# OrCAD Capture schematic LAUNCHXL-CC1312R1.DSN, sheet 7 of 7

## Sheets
7 1_RF: size A3
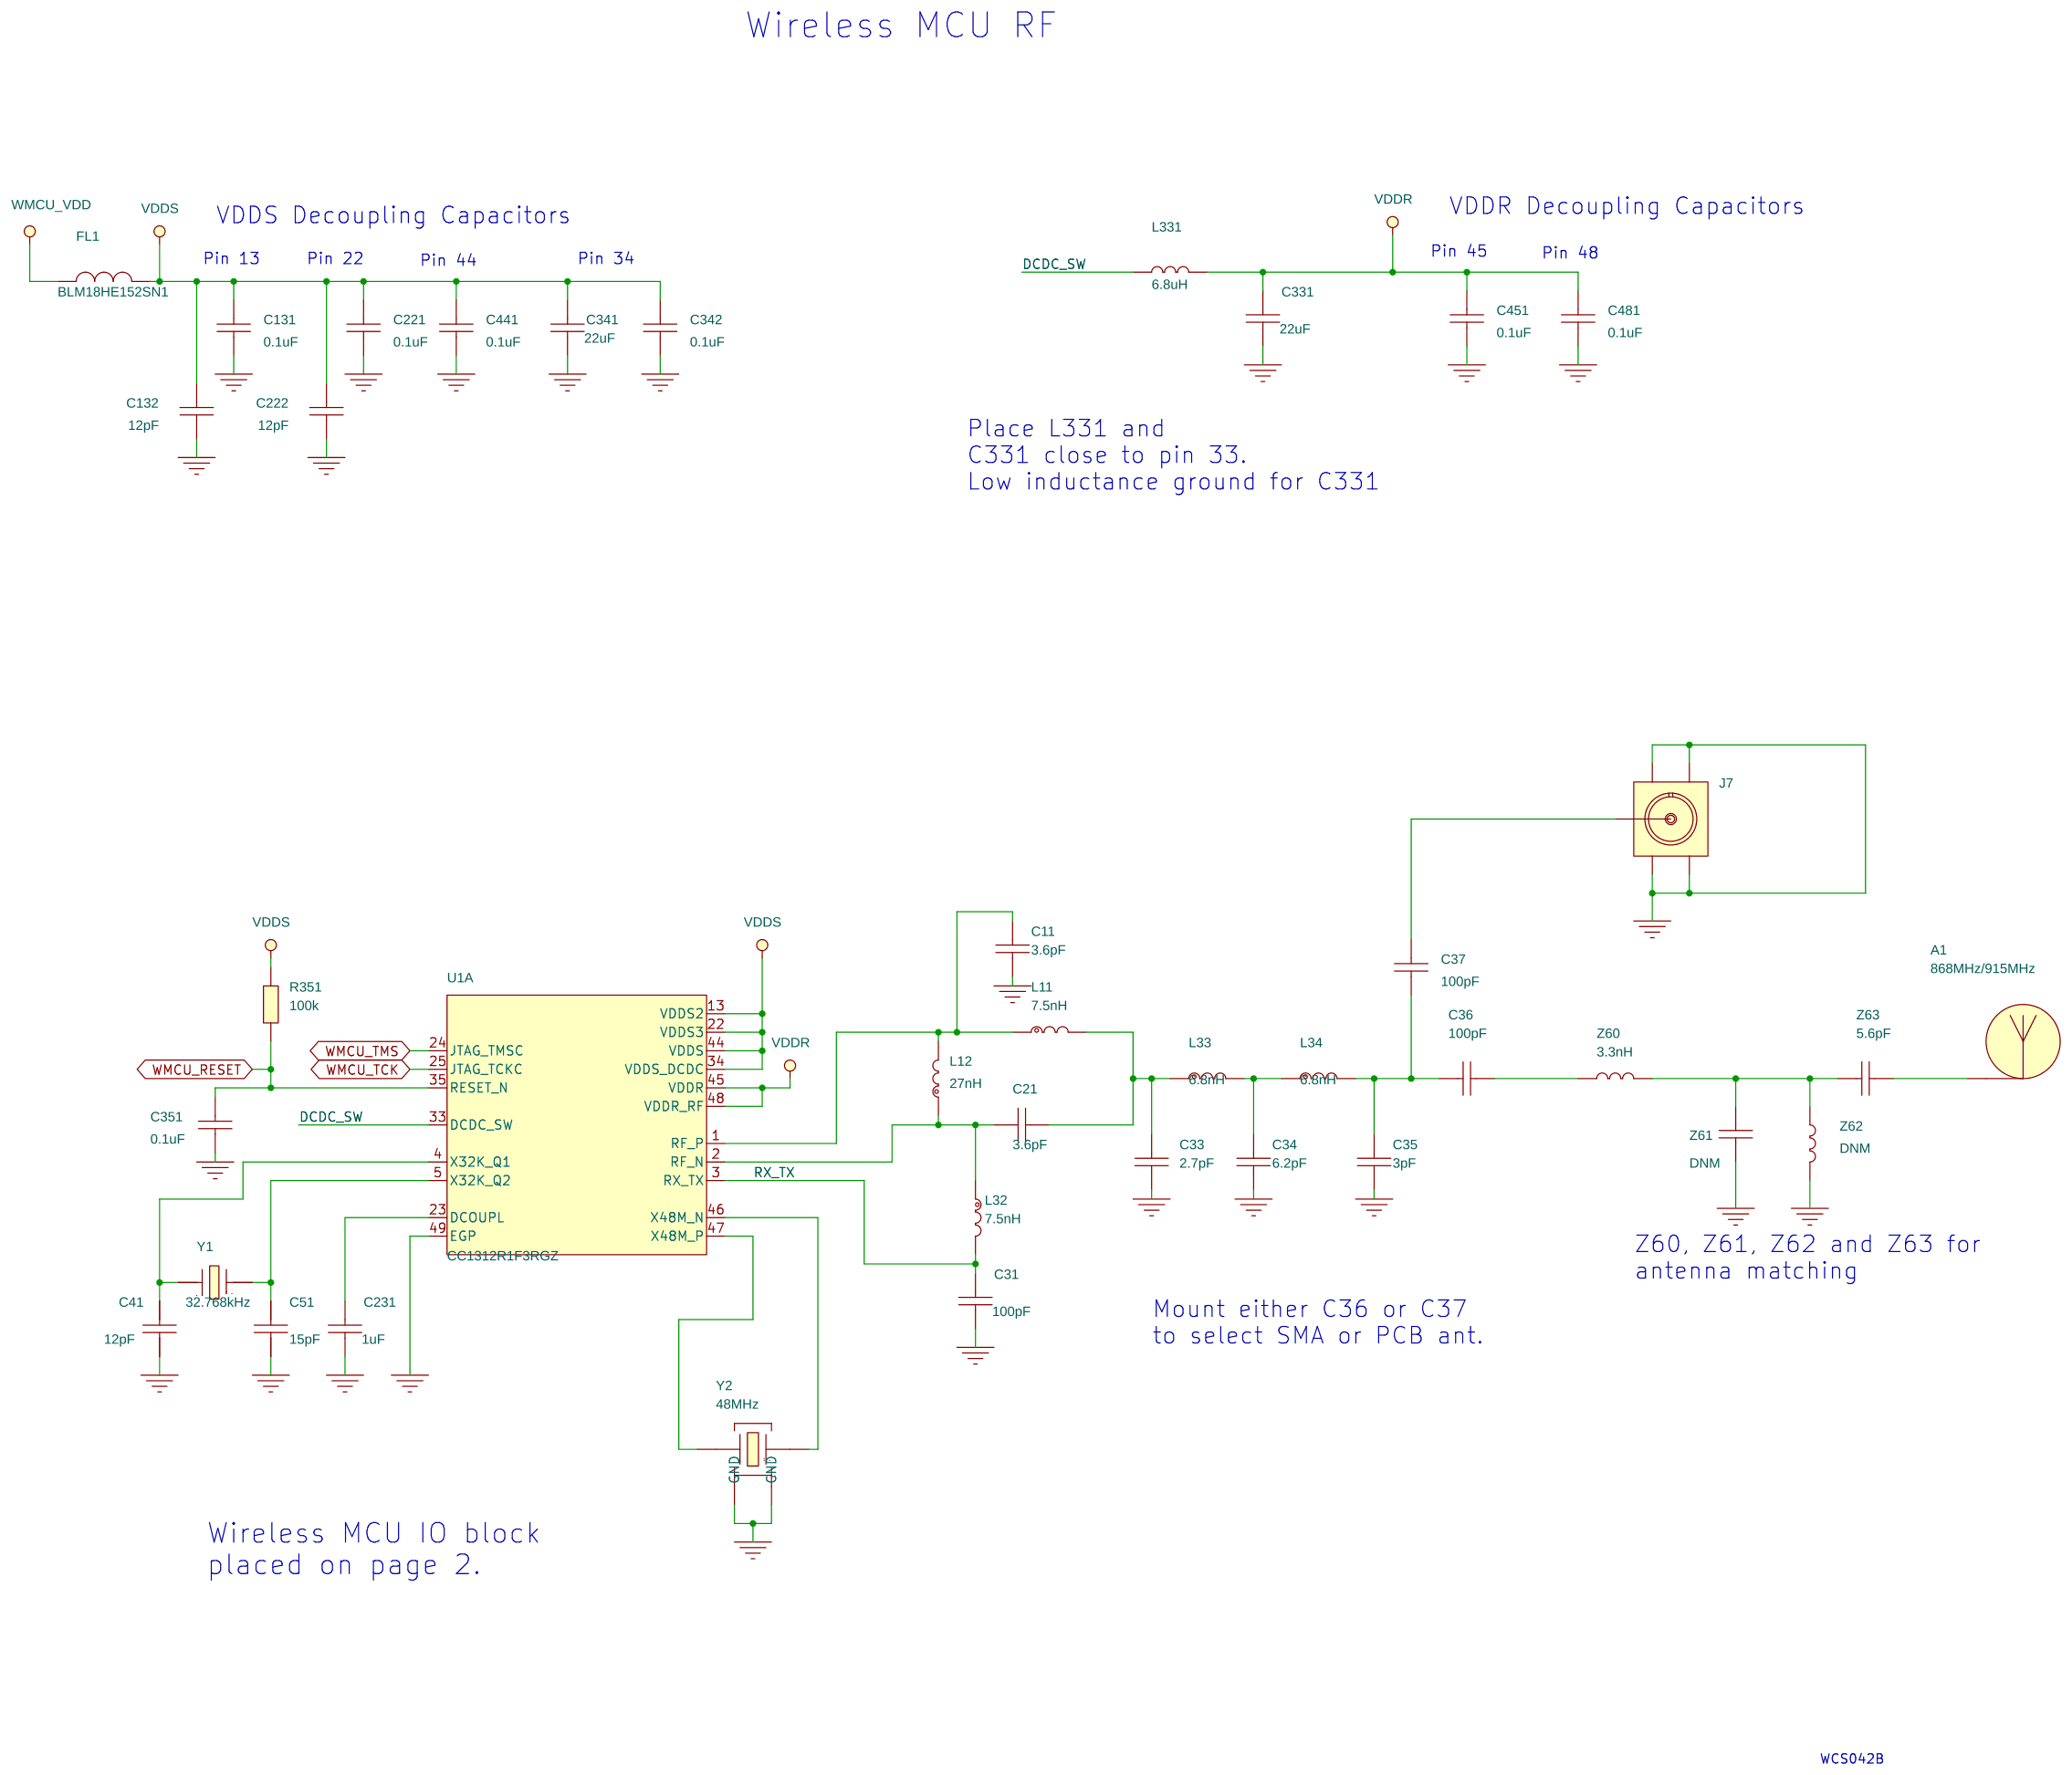
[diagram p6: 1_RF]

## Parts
sheet 1_RF
A1  868MHz/915MHz  [ANTENNA_DN024N]
C11  3.6pF  [CAPC1005X60B2N]
C21  3.6pF  [CAPC1005X60B2N]
C31  100pF  [CAPC1005X60B2N]
C33  2.7pF  [CAPC1005X60B2N]
C34  6.2pF  [CAPC1005X60B2N]
C35  3pF  [CAPC1005X60B2N]
C36  100pF  [CAPC1005X60B2N]
C37  100pF  [CAPC1005X60B2N]
C41  12pF  [CAPC1005X60B2N]
C51  15pF  [CAPC1005X60B2N]
C131  0.1uF  [CAPC1005X60B2N]
C132  12pF  [CAPC1005X60B2N]
C221  0.1uF  [CAPC1005X60B2N]
C222  12pF  [CAPC1005X60B2N]
C231  1uF  [CAPC1005X60B2N]
C331  22uF  [CAPC1608X100A2N]
C341  22uF  [CAPC1608X100A2N]
C342  0.1uF  [CAPC1005X60B2N]
C351  0.1uF  [CAPC1005X60B2N]
C441  0.1uF  [CAPC1005X60B2N]
C451  0.1uF  [CAPC1005X60B2N]
C481  0.1uF  [CAPC1005X60B2N]
FL1  BLM18HE152SN1  [FIL_BLM18HE152SN1DL]
J7  SMA-10V21-TGG  [HUSTSAN_SMA10V21TGGAN]
L11  7.5nH  [INDC1005X60D2N]
L12  27nH  [INDC1005X60D2N]
L32  7.5nH  [INDC1005X60D2N]
L33  6.8nH  [INDC1005X60D2N]
L34  6.8nH  [INDC1005X60D2N]
L331  6.8uH  [INDC2012X150A2N]
R351  100k  [RESC1005X40B2N]
Y1  32.768kHz  [XTAL_FC-135N]
Y2  48MHz  [OSCCC200X160X45-4A2N]
Z60  3.3nH  [INDC1005X60B2N]
Z61  DNM  [CAPC1005X60B2N]
Z62  DNM  [IND_LQW15AN]
Z63  5.6pF  [CAPC0603X35B2N]
sheet 2_Peripherals
U1  CC1312R1F3RGZ  [QFNFC50P700X700X100-49A2N]  (sections A,B)

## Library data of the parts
A1 = ANTENNA_PCB_0: ANTENNA, NON COMPONENT, DUAL BAND OPTION - 868MHz/2440MHz, NOT APPLY; AutoDoc File: https://notefied-dynamic-precision.com/DB/Apps/Desktop/Item/Object.aspx?id=96668; BU Name: DYNAMIC PRECISION GDANSK; Budget Currency: N/A; Budget Price: N/A; Client Status: UNDER_REVIEW; Country of Origin: MISSING INFO; Datasheet URL 1: http://www.ti.com/lit/an/swra227e/swra227e.pdf; Datasheet URL 2: N/A; Frequency: 868MHz/2440MHz; Last Time Buy: N/A; Lead Time: N/A; Max Oper Temp: N/A; Min Oper Temp: N/A; Mounting Type: NOT APPLY; Packing Size: N/A; Packing Type: N/A; Part Number: 13-01029; Part Type: MECHANIC\ANTENNA\NON_COMPONENT; Revision: R001; RoHS Status: MISSING_INFO; Vendor: TEXAS INSTRUMENTS; Vendor Part Number: DN024; Vendor Part Status: ACTIVE; Weight: N/A
C11 C21 = CAPACITOR: CAPACITOR, CERAMIC C0G/NP0, 3.6pF, 50V, -0.25pF/+0.25pF, -55DEGC/+125DEGC, 0402, SMD; AutoDoc File: https://notefied-dynamic-precision.com/DB/Apps/Desktop/Item/Object.aspx?id=113359; BU Name: TEXAS INSTRUMENTS NORWAY; Budget Currency: EUR; Budget Price: 0.006; Country of Origin: MISSING INFO; Datasheet URL 1: http://psearch.murata.com/capacitor/product/GRM1555C1H3R6CA01%23.pdf; Datasheet URL 2: http://search.murata.co.jp/Ceramy/image/img/w_hinm/L0005E.pdf; Dielectric Type: C0G/NP0; Last Time Buy: N/A; Lead Time: 12; Max Oper Temp: +125DEGC; Max Tol: +0.25pF; Min Oper Temp: -55DEGC; Min Tol: -0.25pF; Mounting Type: SMD; PCB Package: 0402; Packing Size: 10000; Packing Type: TAPE_&_REEL; Part Number: 02-07631; Part Type: CAPACITOR\CERAMIC\0402\STANDARD; REACH/SVHC_COMPLIANCE: COMPLIANT; REACH/SVHC_DETAILS: SVHC LIST VERSION Jun 20, 2016; REACH/SVHC_SOURCE: REACH DECLARATION; REACH/SVHC_STATUS: UNAFFECTED; Revision: R000; RoHS Status: ROHS_COMPLIANT; Rtd Voltage: 50V; Vendor: MURATA; Vendor Part Number: GRM1555C1H3R6CA01D; Vendor Part Status: ACTIVE; Weight: 0.0016g
C31 C36 C37 = CAPACITOR: CAPACITOR, CERAMIC C0G/NP0, 100pF, 50V, -5%/+5%, -55DEGC/+125DEGC, 0402, SMD; AutoDoc File: https://notefied-dynamic-precision.com/DB/Apps/Desktop/Item/Object.aspx?id=113347; BU Name: TEXAS INSTRUMENTS NORWAY; Budget Currency: EUR; Budget Price: 0.004; Country of Origin: CHINA; Datasheet URL 1: http://psearch.murata.com/capacitor/product/GRM1555C1H101JA01%23.pdf; Datasheet URL 2: http://search.murata.co.jp/Ceramy/image/img/w_hinm/L0005E.pdf; Dielectric Type: C0G/NP0; Last Time Buy: N/A; Lead Time: 12; Max Oper Temp: +125DEGC; Max Tol: +5%; Min Oper Temp: -55DEGC; Min Tol: -5%; Mounting Type: SMD; PCB Package: 0402; Packing Size: 10000; Packing Type: TAPE_&_REEL; Part Number: 02-07619; Part Type: CAPACITOR\CERAMIC\0402\STANDARD; REACH/SVHC_COMPLIANCE: COMPLIANT; REACH/SVHC_DETAILS: SVHC LIST VERSION Dec 17, 2015; REACH/SVHC_SOURCE: REACH DECLARATION; REACH/SVHC_STATUS: UNAFFECTED; Revision: R000; RoHS Status: ROHS_COMPLIANT; Rtd Voltage: 50V; Vendor: MURATA; Vendor Part Number: GRM1555C1H101JA01D; Vendor Part Status: ACTIVE; Weight: 0.0016g
C33 = CAPACITOR: CAPACITOR, CERAMIC C0G/NP0, 2.7pF, 50V, -0.25pF/+0.25pF, -55DEGC/+125DEGC, 0402, SMD; AutoDoc File: https://notefied-dynamic-precision.com/DB/Apps/Desktop/Item/Object.aspx?id=113356; BU Name: TEXAS INSTRUMENTS NORWAY; Budget Currency: EUR; Budget Price: 0.007; Country of Origin: PHILIPPINES; Datasheet URL 1: http://psearch.murata.com/capacitor/product/GRM1555C1H2R7CA01%23.pdf; Datasheet URL 2: http://search.murata.co.jp/Ceramy/image/img/w_hinm/L0005E.pdf; Dielectric Type: C0G/NP0; Last Time Buy: N/A; Lead Time: 12; Max Oper Temp: +125DEGC; Max Tol: +0.25pF; Min Oper Temp: -55DEGC; Min Tol: -0.25pF; Mounting Type: SMD; PCB Package: 0402; Packing Size: 10000; Packing Type: TAPE_&_REEL; Part Number: 02-07628; Part Type: CAPACITOR\CERAMIC\0402\STANDARD; REACH/SVHC_COMPLIANCE: COMPLIANT; REACH/SVHC_DETAILS: SVHC LIST VERSION Dec 17, 2015; REACH/SVHC_SOURCE: REACH DECLARATION; REACH/SVHC_STATUS: UNAFFECTED; Revision: R000; RoHS Status: ROHS_COMPLIANT; Rtd Voltage: 50V; Vendor: MURATA; Vendor Part Number: GRM1555C1H2R7CA01D; Vendor Part Status: ACTIVE; Weight: 0.0016g
C34 = CAPACITOR: CAPACITOR, CERAMIC C0G/NP0, 6.2pF, 50V, -0.25pF/+0.25pF, -55DEGC/+125DEGC, 0402, SMD; AutoDoc File: https://notefied-dynamic-precision.com/DB/Apps/Desktop/Item/Object.aspx?id=113354; BU Name: TEXAS INSTRUMENTS NORWAY; Budget Currency: EUR; Budget Price: 0.007; Country of Origin: PHILIPPINES; Datasheet URL 1: http://psearch.murata.com/capacitor/product/GRM1555C1H6R2CA01%23.pdf; Datasheet URL 2: http://search.murata.co.jp/Ceramy/image/img/w_hinm/L0005E.pdf; Dielectric Type: C0G/NP0; Last Time Buy: N/A; Lead Time: 14; Max Oper Temp: +125DEGC; Max Tol: +0.25pF; Min Oper Temp: -55DEGC; Min Tol: -0.25pF; Mounting Type: SMD; PCB Package: 0402; Packing Size: 10000; Packing Type: TAPE_&_REEL; Part Number: 02-07626; Part Type: CAPACITOR\CERAMIC\0402\STANDARD; REACH/SVHC_COMPLIANCE: COMPLIANT; REACH/SVHC_DETAILS: SVHC LIST VERSION Dec 17, 2015; REACH/SVHC_SOURCE: REACH DECLARATION; REACH/SVHC_STATUS: UNAFFECTED; Revision: R000; RoHS Status: ROHS_COMPLIANT; Rtd Voltage: 50V; Vendor: MURATA; Vendor Part Number: GRM1555C1H6R2CA01D; Vendor Part Status: ACTIVE; Weight: 0.0016g
C35 = CAPACITOR: CAPACITOR, CERAMIC C0G/NP0, 3pF, 50V, -0.25pF/+0.25pF, -55DEGC/+125DEGC, 0402, SMD; AutoDoc File: https://notefied-dynamic-precision.com/DB/Apps/Desktop/Item/Object.aspx?id=113353; BU Name: TEXAS INSTRUMENTS NORWAY; Budget Currency: EUR; Budget Price: 0.006; Country of Origin: PHILIPPINES; Datasheet URL 1: http://psearch.murata.com/capacitor/product/GRM1555C1H3R0CA01%23.pdf; Datasheet URL 2: http://search.murata.co.jp/Ceramy/image/img/w_hinm/L0005E.pdf; Dielectric Type: C0G/NP0; Last Time Buy: N/A; Lead Time: 16; Max Oper Temp: +125DEGC; Max Tol: +0.25pF; Min Oper Temp: -55DEGC; Min Tol: -0.25pF; Mounting Type: SMD; PCB Package: 0402; Packing Size: 10000; Packing Type: TAPE_&_REEL; Part Number: 02-07625; Part Type: CAPACITOR\CERAMIC\0402\STANDARD; REACH/SVHC_COMPLIANCE: COMPLIANT; REACH/SVHC_DETAILS: SVHC LIST VERSION Dec 17, 2015; REACH/SVHC_SOURCE: REACH DECLARATION; REACH/SVHC_STATUS: UNAFFECTED; Revision: R000; RoHS Status: ROHS_COMPLIANT; Rtd Voltage: 50V; Vendor: MURATA; Vendor Part Number: GRM1555C1H3R0CA01D; Vendor Part Status: ACTIVE; Weight: 0.0016g
C41 = CAPACITOR: CAPACITOR, CERAMIC C0G/NP0, 12pF, 50V, -5%/+5%, -55DEGC/+125DEGC, 0402, SMD; AutoDoc File: https://notefied-dynamic-precision.com/DB/Apps/Desktop/Item/Object.aspx?id=113345; BU Name: TEXAS INSTRUMENTS NORWAY; Budget Currency: EUR; Budget Price: 0.007; Country of Origin: PHILIPPINES; Datasheet URL 1: http://psearch.murata.com/capacitor/product/GRM1555C1H120JA01%23.pdf; Datasheet URL 2: http://search.murata.co.jp/Ceramy/image/img/w_hinm/L0005E.pdf; Definied Quality: INDUSTRIAL; Dielectric Type: C0G/NP0; Esd Level: N/A; Last Time Buy: N/A; Lead Time: 12; LifeCycle Status: ACTIVE; MPN: CAPACITOR_0402_12pF_C0G/NP0_M_+/-5%_50V; MPN Status: ACTIVE; MSL: N/A; MTBF: N/A; MTBF Standard: N/A; Manufacturer: MANUFACTURER SELECTION; Max Oper Temp: +125DEGC; Max Tol: +5%; Min Oper Temp: -55DEGC; Min Tol: -5%; Mounting Type: SMD; NOTE Status: PREFERRED; Old Footprint: CAPC1005X60N; PCB Package: 0402; Packing Size: 10000; Packing Type: TAPE_&_REEL; Part Number: 02-07617; Part Type: CAPACITOR\CERAMIC\0402\STANDARD; REACH/SVHC_COMPLIANCE: COMPLIANT; REACH/SVHC_DETAILS: SVHC LIST VERSION Dec 17, 2015; REACH/SVHC_SOURCE: REACH DECLARATION; REACH/SVHC_STATUS: UNAFFECTED; Revision: R000; RoHS Status: ROHS_COMPLIANT; Rtd Voltage: 50V; Vendor: MURATA; Vendor Part Number: GRM1555C1H120JA01D; Vendor Part Status: ACTIVE; WEIGHT: 0.0016g
C51 = CAPACITOR: CAPACITOR, CERAMIC C0G/NP0, 15pF, 50V, -5%/+5%, -55DEGC/+125DEGC, 0402, SMD; AutoDoc File: https://notefied-dynamic-precision.com/DB/Apps/Desktop/Item/Object.aspx?id=114571; BU Name: TEXAS INSTRUMENTS NORWAY; Budget Currency: EUR; Budget Price: 0.006; Client Status: UNDER_REVIEW; Country of Origin: PHILIPPINES; Datasheet URL 1: http://psearch.murata.com/capacitor/product/GRM1555C1H150JA01%23.pdf; Datasheet URL 2: http://psearch.en.murata.com/capacitor/product/GRM1555C1H150JA01%23.html; Dielectric Type: C0G/NP0; Last Time Buy: N/A; Lead Time: 12; Max Oper Temp: +125DEGC; Max Tol: +5%; Min Oper Temp: -55DEGC; Min Tol: -5%; Mounting Type: SMD; PCB Package: 0402; Packing Size: 10000; Packing Type: TAPE_&_REEL; Part Number: 02-07776; Part Type: CAPACITOR\CERAMIC\0402\STANDARD; REACH/SVHC_COMPLIANCE: COMPLIANT; REACH/SVHC_DETAILS: SVHC List Version Jan 12, 2017; REACH/SVHC_SOURCE: REACH DECLARATION; REACH/SVHC_STATUS: UNAFFECTED; Revision: R001; RoHS Status: ROHS_COMPLIANT; Rtd Voltage: 50V; Vendor: MURATA; Vendor Part Number: GRM1555C1H150JA01D; Vendor Part Status: ACTIVE; Weight: 0.0016g
C131 C221 C342 C351 C441 C451 C481 = CAPACITOR: CAPACITOR, CERAMIC X7R, 0.1uF, 25V, -10%/+10%, -55DEGC/+125DEGC, 0402, SMD; AutoDoc File: https://notefied-dynamic-precision.com/DB/Apps/Desktop/Item/Object.aspx?id=115293; BU Name: TEXAS INSTRUMENTS NORWAY; Client Status: UNDER_REVIEW; Datasheet URL 1: http://psearch.en.murata.com/capacitor/product/GRM155R71E104KE14%23.pdf; Datasheet URL 2: http://search.murata.co.jp/Ceramy/image/img/w_hinm/L0005E.pdf; Dielectric Type: X7R; Last Time Buy: N/A; LifeCycle Status: ACTIVE; MPN: GRM155R70J104KA01D; MPN Status: ACTIVE; Manufacturer: MURATA; Max Oper Temp: +125DEGC; Max Tol: +10%; Min Oper Temp: -55DEGC; Min Tol: -10%; Mounting Type: SMD; NOTE Status: PREFERRED; Old Footprint: CAPC1005X60N,0402; PCB Package: 0402; Packing Size: 10000; Packing Type: TAPE_&_REEL; Part Number: 02-07861; Part Type: CAPACITOR\CERAMIC\0402\STANDARD; REACH/SVHC_COMPLIANCE: COMPLIANT; REACH/SVHC_DETAILS: SVHC LIST VERSION Jun 20, 2016; REACH/SVHC_SOURCE: REACH DECLARATION; REACH/SVHC_STATUS: UNAFFECTED; Revision: R002; RoHS Status: ROHS_COMPLIANT; Rtd Voltage: 25V; Vendor: MURATA; Vendor Part Number: GRM155R71E104KE14D; Vendor Part Status: ACTIVE; WEIGHT: 0.0016g
C132 C222 = CAPACITOR: CAPACITOR, CERAMIC C0G/NP0, 12pF, 50V, -5%/+5%, -55DEGC/+125DEGC, 0402, SMD; AutoDoc File: https://notefied-dynamic-precision.com/DB/Apps/Desktop/Item/Object.aspx?id=113345; BU Name: TEXAS INSTRUMENTS NORWAY; Budget Currency: EUR; Budget Price: 0.007; Country of Origin: PHILIPPINES; Datasheet URL 1: http://psearch.murata.com/capacitor/product/GRM1555C1H120JA01%23.pdf; Datasheet URL 2: http://search.murata.co.jp/Ceramy/image/img/w_hinm/L0005E.pdf; Dielectric Type: C0G/NP0; Last Time Buy: N/A; Lead Time: 12; MPN: GRM1555C1H6R8CA01D; MPN Status: ACTIVE; Manufacturer: MURATA; Max Oper Temp: +125DEGC; Max Tol: +5%; Min Oper Temp: -55DEGC; Min Tol: -5%; Mounting Type: SMD; NOTE Status: PREFERRED; Old Footprint: CAPC1005X60N; PCB Package: 0402; Packing Size: 10000; Packing Type: TAPE_&_REEL; Part Number: 02-07617; Part Type: CAPACITOR\CERAMIC\0402\STANDARD; REACH/SVHC_COMPLIANCE: COMPLIANT; REACH/SVHC_DETAILS: SVHC LIST VERSION Dec 17, 2015; REACH/SVHC_SOURCE: REACH DECLARATION; REACH/SVHC_STATUS: UNAFFECTED; Revision: R000; RoHS Status: ROHS_COMPLIANT; Rtd Voltage: 50V; Vendor: MURATA; Vendor Part Number: GRM1555C1H120JA01D; Vendor Part Status: ACTIVE; WEIGHT: 0.0016g
C231 = CAPACITOR: CAPACITOR, CERAMIC X5R, 1uF, 16V, -10%/+10%, -55DEGC/+85DEGC, 0402, SMD; AutoDoc File: https://notefied-dynamic-precision.com/DB/Apps/Desktop/Item/Object.aspx?id=115295; BU Name: TEXAS INSTRUMENTS NORWAY; Client Status: UNDER_REVIEW; Datasheet URL 1: http://psearch.en.murata.com/capacitor/product/GRM155R61C105KA12%23.pdf; Datasheet URL 2: http://search.murata.co.jp/Ceramy/image/img/w_hinm/L0005E.pdf; Definied Quality: INDUSTRIAL; Dielectric Type: X5R; Esd Level: N/A; Last Time Buy: N/A; MPN: GRM155R61A105KE15D; MPN Status: ACTIVE; MSL: 1; MTBF: N/A; MTBF Standard: N/A; Manufacturer: MURATA; Max Oper Temp: +85DEGC; Max Tol: +10%; Min Oper Temp: -55DEGC; Min Tol: -10%; Mounting Type: SMD; NOTE Status: PREFERRED; Old Footprint: CAPC1005X60N,0402; PCB Package: 0402; Packing Size: 10000; Packing Type: TAPE_&_REEL; Part Number: 02-07863; Part Type: CAPACITOR\CERAMIC\0402\STANDARD; REACH/SVHC_COMPLIANCE: COMPLIANT; REACH/SVHC_DETAILS: SVHC LIST VERSION Jun 20, 2016; REACH/SVHC_SOURCE: REACH DECLARATION; REACH/SVHC_STATUS: UNAFFECTED; Revision: R002; RoHS Status: ROHS_COMPLIANT; Rtd Voltage: 16V; Vendor: MURATA; Vendor Part Number: GRM155R61C105KA12D; Vendor Part Status: ACTIVE; WEIGHT: 0.0016g
C331 C341 = CAPACITOR: CAPACITOR, CERAMIC, X5R, 22uF, 6.3V, -20%/+20%, -55DEGC/+85DEGC, 0603, SMD; ALT_SYMBOLS: CAPC1608X100A2L,CAPC1608X100A2M; AutoDoc File: https://notefied-dynamic-precision.com/DB/Apps/Desktop/Item/Object.aspx?id=104385; BU Name: DYNAMIC PRECISION GDANSK; Budget Currency: EUR; Budget Price: 0.062; Client Status: UNDER_REVIEW; Country of Origin: JAPAN; Datasheet URL 1: http://psearch.murata.com/capacitor/product/GRM188R60J226MEA0%23.pdf; Datasheet URL 2: http://search.murata.co.jp/Ceramy/image/img/w_hinm/L0005E.pdf; Definied Quality: INDUSTRIAL; Dielectric Type: X5R; Esd Level: N/A; Last Time Buy: N/A; Lead Time: 26; MPN: GRM188R60J106ME47D; MPN Status: NRND; MSL: 1; MTBF: N/A; MTBF Standard: N/A; Manufacturer: MURATA; Max Oper Temp: +85DEGC; Max Tol: +20%; Min Oper Temp: -55DEGC; Min Tol: -20%; Mounting Type: SMD; NOTE Status: PREFERRED; Old Footprint: CAPC1608X90N; PCB Package: 0603; Packing Size: 4000; Packing Type: TAPE_&_REEL; Part Number: 02-07053; Part Type: CAPACITOR\CERAMIC\0603\STANDARD; REACH/SVHC_COMPLIANCE: COMPLIANT; REACH/SVHC_DETAILS: SVHC LIST VERSION Dec 17, 2015; REACH/SVHC_SOURCE: REACH DECLARATION; REACH/SVHC_STATUS: UNAFFECTED; Revision: R001; RoHS Status: ROHS_COMPLIANT; Rtd Voltage: 6.3V; Vendor: MURATA; Vendor Part Number: GRM188R60J226MEA0D; Vendor Part Status: ACTIVE; WEIGHT: 0.0091g
FL1 = FILTER_2PIN: FILTER, EMI, 1500@100MHz, -55DEGC/+125DEGC, 0603, SMD; ALT_SYMBOLS: FIL_BLM18HE152SN1DL,FIL_BLM18HE152SN1DM; AutoDoc File: http://notefied-dynamic-precision.com/DB/Apps/Desktop/Item/Object.aspx?id=85575; Budget Currency: EUR; Budget Price: 0.085; Datasheet URL 1: http://search.murata.co.jp/Ceramy/image/img/PDF/ENG/L0110S0101BLM18H.pdf; Datasheet URL 2: http://search.murata.co.jp/Ceramy/image/img/PDF/ENG/L0110S0101BLM18H.pdf; FPLIST: FIL_BLM18HE152SN1DN,FIL_BLM18HE152SN1DL,FIL_BLM18HE152SN1DM; Impedance: 1500@100MHz; Lead Time: 26; MPN: BLM18HE152SN1D; MPN Status: ACTIVE; Manufacturer: MURATA; Max Oper Temp: +125DEGC; Max Tol: +25%; Min Oper Temp: -55DEGC; Min Tol: -25%; Mounting Type: SMD; NOTE Status: PREFERRED; Old Footprint: FIL_BLM18HE152SN1DN; PCB Package: 0603; Packing Size: 4000; Packing Type: TAPE_&_REEL; Part Number: 04-00470; Part Type: FILTER\EMI\0603; Revision: R001; RoHS Status: ROHS_COMPLIANT; Rtd Current: 0.5A; WEIGHT: 0.006g
J7 = CONN_COAX_1_4: CONNECTOR, COAX, RF, FEMALE, STRAIGHT, 1 PIN, SMD; ALT_SYMBOLS: HUSTSAN_SMA10V21TGGL,HUSTSAN_SMA10V21TGGM; AutoDoc File: https://notefied-dynamic-precision.com/DB/Apps/Desktop/Item/Object.aspx?id=84956; BU Name: DYNAMIC PRECISION GDANSK; Budget Currency: N/A; Budget Price: N/A; Client Status: UNDER_REVIEW; Country of Origin: TAIWAN; Datasheet URL 1: http://www.hustsan.com.tw/uploaddir/product/SMA-10V21.pdf; Datasheet URL 2: http://www.hustsan.com.tw/cgi-bin/productfn/pdt_detail_lst.pl?ProdID=143; FPLIST: HUSTSAN_SMA10V21TGGAN,HUSTSAN_SMA10V21TGGN; Last Time Buy: N/A; Lead Time: N/A; Mounting Type: SMD; No Of Pos: 1; Packing Size: 350; Packing Type: TAPE_&_REEL; Part Number: 06-02188; Part Type: CONNECTOR\COAX\RF; REACH/SVHC_COMPLIANCE: COMPLIANT; REACH/SVHC_DETAILS: SVHC LIST VERSION Jan 12, 2016; REACH/SVHC_SOURCE: REACH DECLARATION; REACH/SVHC_STATUS: UNAFFECTED; Revision: R004; RoHS Status: ROHS_COMPLIANT; Vendor: HUS-TSAN; Vendor Part Status: ACTIVE; Weight: N/A
L11 L32 = INDUCTOR_HOR_1_1: INDUCTOR, RF, CHIP, NON-MAGNETIC CORE, 7.5nH, -5%/+5%, 0.3A, -55DEGC/+125DEGC, 0402, SMD; AutoDoc File: https://notefied-dynamic-precision.com/DB/Apps/Desktop/Item/Object.aspx?id=113370; BU Name: TEXAS INSTRUMENTS NORWAY; Budget Currency: EUR; Budget Price: 0.03; Client Status: UNDER_REVIEW; Core Material: NON-MAGNETIC; Country of Origin: MISSING INFO; Datasheet URL 1: http://psearch.murata.com/inductor/product/LQG15HS7N5J02%23.pdf; Datasheet URL 2: http://www.murata.com/~/media/webrenewal/support/library/catalog/products/inductor/chip/o05e.ashx; Frequency: 4.2GHz; Last Time Buy: N/A; Lead Time: 10; Max Oper Temp: +125DEGC; Max Tol: +5%; Min Oper Temp: -55DEGC; Min Tol: -5%; Mounting Type: SMD; PCB Package: 0402; Packing Size: 10000; Packing Type: TAPE_&_REEL; Part Number: 03-07533; Part Type: INDUCTOR\RF\CHIP\0402; REACH/SVHC_COMPLIANCE: COMPLIANT; REACH/SVHC_DETAILS: SVHC LIST VERSION Dec 17, 2015; REACH/SVHC_SOURCE: REACH DECLARATION; REACH/SVHC_STATUS: UNAFFECTED; Resistance: 0.24; Revision: R001; RoHS Status: ROHS_COMPLIANT; Rtd Current: 0.3A; Vendor: MURATA; Vendor Part Number: LQG15HS7N5J02D; Vendor Part Status: ACTIVE; Weight: 0.001g
L12 = INDUCTOR_HOR_1_0: INDUCTOR, RF, CHIP, NON-MAGNETIC CORE, 27nH, -5%/+5%, 0.3A, -55DEGC/+125DEGC, 0402, SMD; AutoDoc File: https://notefied-dynamic-precision.com/DB/Apps/Desktop/Item/Object.aspx?id=113365; BU Name: TEXAS INSTRUMENTS NORWAY; Budget Currency: EUR; Budget Price: 0.03; Client Status: UNDER_REVIEW; Core Material: NON-MAGNETIC; Country of Origin: JAPAN,SINGAPORE; Datasheet URL 1: http://psearch.murata.com/inductor/product/LQG15HS27NJ02%23.pdf; Datasheet URL 2: http://www.murata.com/~/media/webrenewal/support/library/catalog/products/inductor/chip/o05e.ashx; Frequency: 1700MHz; Last Time Buy: N/A; Lead Time: 9; Max Oper Temp: +125DEGC; Max Tol: +5%; Min Oper Temp: -55DEGC; Min Tol: -5%; Mounting Type: SMD; PCB Package: 0402; Packing Size: 10000; Packing Type: TAPE_&_REEL; Part Number: 03-07528; Part Type: INDUCTOR\RF\CHIP\0402; REACH/SVHC_COMPLIANCE: COMPLIANT; REACH/SVHC_DETAILS: SVHC LIST VERSION Dec 17, 2015; REACH/SVHC_SOURCE: REACH DECLARATION; REACH/SVHC_STATUS: UNAFFECTED; Resistance: 0.46; Revision: R001; RoHS Status: ROHS_COMPLIANT; Rtd Current: 0.3A; Vendor: MURATA; Vendor Part Number: LQG15HS27NJ02D; Vendor Part Status: ACTIVE; Weight: 0.001g
L33 L34 = INDUCTOR_HOR_1_1: INDUCTOR, RF, CHIP, NON-MAGNETIC CORE, 6.8nH, -5%/+5%, 0.3A, -55DEGC/+125DEGC, 0402, SMD; AutoDoc File: https://notefied-dynamic-precision.com/DB/Apps/Desktop/Item/Object.aspx?id=113369; BU Name: TEXAS INSTRUMENTS NORWAY; Budget Currency: EUR; Budget Price: 0.03; Client Status: UNDER_REVIEW; Core Material: NON-MAGNETIC; Country of Origin: JAPAN,SINGAPORE; Datasheet URL 1: http://psearch.murata.com/inductor/product/LQG15HS6N8J02%23.pdf; Datasheet URL 2: http://www.murata.com/~/media/webrenewal/support/library/catalog/products/inductor/chip/o05e.ashx; Frequency: 4.5GHz; Last Time Buy: N/A; Lead Time: 9; Max Oper Temp: +125DEGC; Max Tol: +5%; Min Oper Temp: -55DEGC; Min Tol: -5%; Mounting Type: SMD; PCB Package: 0402; Packing Size: 10000; Packing Type: TAPE_&_REEL; Part Number: 03-07532; Part Type: INDUCTOR\RF\CHIP\0402; REACH/SVHC_COMPLIANCE: COMPLIANT; REACH/SVHC_DETAILS: SVHC LIST VERSION Dec 17, 2015; REACH/SVHC_SOURCE: REACH DECLARATION; REACH/SVHC_STATUS: UNAFFECTED; Resistance: 0.24; Revision: R001; RoHS Status: ROHS_COMPLIANT; Rtd Current: 0.3A; Vendor: MURATA; Vendor Part Number: LQG15HS6N8J02D; Vendor Part Status: ACTIVE; Weight: 0.001g
L331 = INDUCTOR: INDUCTOR, STANDARD, CHIP, FERRITE CORE, SHIELDED, 6.8uH, -20%/+20%, 1.1A, -55DEGC/+125DEGC, 0805, SMD; ALT_SYMBOLS: INDC2012X150A2L,INDC2012X150A2M; AutoDoc File: https://notefied-dynamic-precision.com/DB/Apps/Desktop/Item/Object.aspx?id=102853; BU Name: DYNAMIC PRECISION GDANSK; Budget Currency: EUR; Budget Price: 0.059; Client Status: UNDER_REVIEW; Core Material: FERRITE; Country of Origin: MISSING INFO; Datasheet URL 1: https://product.tdk.com/info/en/catalog/datasheets/inductor_commercial_decoupling_mlz2012_en.pdf; Datasheet URL 2: N/A; Last Time Buy: N/A; Lead Time: 12; MPN: CKS2125100M-T; MPN Status: ACTIVE; Manufacturer: TAIYO YUDEN; Max Oper Temp: +125DEGC; Max Tol: +20%; Min Oper Temp: -55DEGC; Min Tol: -20%; Mounting Type: SMD; NOTE Status: PREFERRED; Old Footprint: INDC2012X150N; PCB Package: 0805; Packing Size: 4000; Packing Type: TAPE_&_REEL; Part Number: 03-07266; Part Type: INDUCTOR\STANDARD\CHIP\0805; REACH/SVHC_COMPLIANCE: COMPLIANT; REACH/SVHC_DETAILS: SVHC LIST VERSION Dec 17, 2015; REACH/SVHC_SOURCE: REACH DECLARATION; REACH/SVHC_STATUS: UNAFFECTED; Resistance: 0.25; Revision: R002; RoHS Status: ROHS_COMPLIANT; Rtd Current: 1.1A; Vendor: TDK; Vendor Part Number: MLZ2012N6R8LT000; Vendor Part Status: ACTIVE; Weight: 0.01g
R351 = RESISTOR: RESISTOR, THICK FILM, 100k, -5%/+5%, 0.063W, 50V, -55DEGC/+155DEGC, 0402, SMD; AutoDoc File: https://notefied-dynamic-precision.com/DB/Apps/Desktop/Item/Object.aspx?id=114565; BU Name: TEXAS INSTRUMENTS NORWAY; Budget Currency: EUR; Budget Price: 0.014; Client Status: UNDER_REVIEW; Country of Origin: UNITED STATES; Datasheet URL 1: http://www.vishay.com/docs/20035/dcrcwe3.pdf; Datasheet URL 2: N/A; Definied Quality: INDUSTRIAL; Esd Level: N/A; Last Time Buy: N/A; Lead Time: 18; LifeCycle Status: ACTIVE; MPN: RESISTOR_0402_100k_+/-1%_50V_0.063W_M_+/-100PPM; MPN Status: ACTIVE; MSL: N/A; MTBF: N/A; MTBF Standard: N/A; Manufacturer: MANUFACTURER SELECTION; Max Oper Temp: +155DEGC; Max TC: +200PPM/DEGC; Max Tol: +5%; Min Oper Temp: -55DEGC; Min TC: -200PPM/DEGC; Min Tol: -5%; Mounting Type: SMD; NOTE Status: PREFERRED; Old Footprint: RESC1005X40N; PCB Package: 0402; Packing Size: 10000; Packing Type: TAPE_&_REEL; Part Number: 01-22492; Part Type: RESISTOR\0402\STANDARD; REACH/SVHC_COMPLIANCE: COMPLIANT; REACH/SVHC_DETAILS: SVHC LIST VERSION Jun 20, 2016; REACH/SVHC_SOURCE: MATERIAL DECLARATION; REACH/SVHC_STATUS: UNAFFECTED; Resistor Type: THICK FILM; Revision: R000; RoHS Status: ROHS_COMPLIANT; Rtd Current: N/A; Rtd Power: 0.063W; Rtd Voltage: 50V; Vendor: VISHAY; Vendor Part Number: CRCW0402100KJNED; Vendor Part Status: ACTIVE; Weight: 0.00065g
Y1 = CRYSTAL: CRYSTAL, RESONATOR, 32.768kHz, -20PPM/+20PPM, -40DEGC/+85DEGC, SMD; ALT_SYMBOLS: XTAL_FC-135L,XTAL_FC-135M; AutoDoc File: http://notefied-dynamic-precision.com/DB/Apps/Desktop/Item/Object.aspx?id=91966; Budget Currency: USD; Budget Price: 1.25375; Capacitance: 7pF; Datasheet URL 1: http://www.eea.epson.com/portal/pls/portal/docs/1/1525528.PDF; Datasheet URL 2: http://www.eea.epson.com/portal/pls/portal/docs/1/1525451.PDF; Definied Quality: INDUSTRIAL; Esd Level: N/A; FPLIST: XTAL_FC-135N,XTAL_FC-135L,XTAL_FC-135M; Last Time Buy: N/A; Lead Time: 10; MPN: FC-135 32.7680KA-AG0; MPN Status: ACTIVE; MSL: N/A; MTBF: N/A; MTBF Standard: N/A; Manufacturer: EPSON; Max Oper Temp: +85DEGC; Max Tol: +20PPM; Min Oper Temp: -40DEGC; Min Tol: -20PPM; Mounting Type: SMD; NOTE Status: PREFERRED; Packing Size: 1000; Packing Type: TAPE_&_REEL; Part Number: 12-00546; Part Type: CRYSTAL\OSCILLATOR\MEMS; Revision: R001; RoHS Status: ROHS_COMPLIANT; WEIGHT: N/A
Y2 = XTAL_4PINS_1_3: CRYSTAL, RESONATOR, 48MHz, -20PPM/+20PPM, -40DEGC/+85DEGC, SMD; ALT_SYMBOLS: OSCCC200X160X45-4A2L,OSCCC200X160X45-4A2M; AutoDoc File: https://notefied-dynamic-precision.com/DB/Apps/Desktop/Item/Object.aspx?id=116071; BU Name: TEXAS INSTRUMENTS NORWAY; Capacitance: 7pF; Client Status: UNDER_REVIEW; Datasheet URL 1: https://notefied-dynamic-precision.com/db/Apps/OpenDocument.aspx?obj=5&docid=247744; Datasheet URL 2: N/A; Last Time Buy: N/A; Max Oper Temp: +85DEGC; Max TC: +20PPM; Max Tol: +10PPM; Min Oper Temp: -40DEGC; Min TC: -20PPM; Min Tol: -10PPM; Mounting Type: SMD; Packing Size: 3000; Packing Type: TAPE_&_REEL; Part Number: 12-01233; Part Type: CRYSTAL\RESONATOR; REACH/SVHC_COMPLIANCE: COMPLIANT; REACH/SVHC_DETAILS: SVHC LIST VERSION Dec , 2012; REACH/SVHC_SOURCE: REACH DECLARATION; REACH/SVHC_STATUS: UNAFFECTED; Revision: R002; RoHS Status: ROHS_COMPLIANT; Rtd Voltage: N/A; Vendor: KYOCERA; Vendor Part Number: CX2016DB48000C0FPLC1; Vendor Part Status: ACTIVE
Z60 = INDUCTOR: INDUCTOR, RF, CHIP, 0402, NON-MAGNETIC CORE, 3.3nH, -0.5nH/+0.5nH, 0.9A, -55DEGC/+125DEGC, 0402, SMD; AutoDoc File: https://notefied-dynamic-precision.com/DB/Apps/Desktop/Item/Object.aspx?id=116884; BU Name: TEXAS INSTRUMENTS NORWAY; Client Status: UNDER_REVIEW; Core Material: NON-MAGNETIC; Datasheet URL 1: http://www.murata.com/~/media/webrenewal/support/library/catalog/products/inductor/chip/o05e.ashx?la=en-gb; Datasheet URL 2: http://psearch.en.murata.com/inductor/product/LQW15AN3N3D10%23.pdf; Frequency: 12GHz; Last Time Buy: N/A; Max Oper Temp: +125DEGC; Max Tol: +0.5nH; Min Oper Temp: -55DEGC; Min Tol: -0.5nH; Mounting Type: SMD; PCB Package: 0402; Packing Size: 10000; Packing Type: TAPE_&_REEL; Part Number: 03-07708; Part Type: INDUCTOR\RF\CHIP\0402; REACH/SVHC_COMPLIANCE: COMPLIANT; REACH/SVHC_DETAILS: SVHC List Version Jan 12, 2017; REACH/SVHC_SOURCE: REACH DECLARATION; REACH/SVHC_STATUS: UNAFFECTED; Resistance: 0.04; Revision: R001; RoHS Status: ROHS_COMPLIANT; Rtd Current: 0.9A; Vendor: MURATA; Vendor Part Number: LQW15AN3N3D10D; Vendor Part Status: ACTIVE; Weight: 0.0008g
Z61 = CAPACITOR: CAPACITOR, CERAMIC, TBD, -55DEGC/+125DEGC, 0402, DNM, SMD; AutoDoc File: https://notefied-dynamic-precision.com/DB/Apps/Desktop/Item/Object.aspx?id=113344; BU Name: TEXAS INSTRUMENTS NORWAY; Budget Currency: USD; Budget Price: 0.00589; Country of Origin: MISSING INFO; Datasheet URL 1: N/A; Datasheet URL 2: N/A; Dielectric Type: MISSING-INFO; Last Time Buy: N/A; Lead Time: N/A; MPN: CAPACITOR_0402_DNM_N/A_M; MPN Status: ACTIVE; Manufacturer: Manufacturer selection; Max Oper Temp: +125DEGC; Min Oper Temp: -55DEGC; Mounting Type: SMD; NOTE Status: PREFERRED; Old Footprint: CAPC1005X60N; PCB Package: 0402; Packing Size: 10000; Packing Type: TAPE_&_REEL; Part Number: 02-07616; Part Type: CAPACITOR\CERAMIC\0402\STANDARD; Revision: R000; RoHS Status: MISSING_INFO; Vendor: MANUFACTURER SELECTION; Vendor Part Number: CAPACITOR_0402_DNM_N/A_M; Vendor Part Status: ACTIVE; Weight: N/A
Z62 = INDUCTOR: INDUCTOR, TBD, 0402, SMD, DNM; ALT_SYMBOLS: IND_LQW15AL,IND_LQW15AM; AutoDoc File: https://notefied-dynamic-precision.com/DB/Apps/Desktop/Item/Object.aspx?id=113982; BU Name: TEXAS INSTRUMENTS NORWAY; Client Status: UNDER_REVIEW; Core Material: MISSING_INFO; Datasheet URL 1: N/A; Datasheet URL 2: N/A; Max Oper Temp: N/A; Min Oper Temp: N/A; Mounting Type: SMD; PCB Package: 0402; Part Number: 03-07582; Part Type: INDUCTOR\RF\CHIP\0402; REACH/SVHC_COMPLIANCE: MISSING_INFO; REACH/SVHC_DETAILS: N/A; REACH/SVHC_SOURCE: N/A; REACH/SVHC_STATUS: MISSING_INFO; Revision: R001; RoHS Status: ROHS_COMPLIANT; Vendor: MANUFACTURER SELECTION; Vendor Part Number: INDUCTOR_TBD_0402_DNM; Vendor Part Status: ACTIVE
Z63 = CAPACITOR: CAPACITOR, CERAMIC C0G/NP0, 5.6pF, 50V, -0.1pF/+0.1pF, -55DEGC/+125DEGC, 0201, SMD; ALT_SYMBOLS: CAPC0603X35B2L,CAPC0603X35B2M; AutoDoc File: https://notefied-dynamic-precision.com/DB/Apps/Desktop/Item/Object.aspx?id=97055; BU Name: DYNAMIC PRECISION GDANSK; Budget Currency: EUR; Budget Price: 0.006; Client Status: UNDER_REVIEW; Country of Origin: MISSING INFO; Datasheet URL 1: http://psearch.murata.com/capacitor/product/GRM0335C1H5R6BA01%23.pdf; Datasheet URL 2: http://psearch.en.murata.com/capacitor/product/GRM0335C1H5R6BA01%23.html; Dielectric Type: C0G/NP0; Last Time Buy: N/A; Lead Time: 18; Max Oper Temp: +125DEGC; Max Tol: +0.1pF; Min Oper Temp: -55DEGC; Min Tol: -0.1pF; Mounting Type: SMD; PCB Package: 0201; Packing Size: 50000; Packing Type: TAPE_&_REEL; Part Number: 02-06170; Part Type: CAPACITOR\CERAMIC\0201\STANDARD; REACH/SVHC_COMPLIANCE: COMPLIANT; REACH/SVHC_DETAILS: SVHC List Version Jan 12, 2017; REACH/SVHC_SOURCE: REACH DECLARATION; REACH/SVHC_STATUS: UNAFFECTED; Revision: R004; RoHS Status: ROHS_COMPLIANT; Rtd Voltage: 50V; Vendor: MURATA; Vendor Part Number: GRM0335C1H5R6BA01J; Vendor Part Status: ACTIVE; Weight: 0.00033g
U1 = IC_RF_CC1312R1F3_VQFN48: IC, MICROCONTROLLER, TEXAS INSTRUMENTS, CUSTOM, CC1312R1F3RGZ, 1.8V TO 3.8V, VQFN48, SMD; ALT_SYMBOLS: QFNFC50P700X700X100-49A2L,QFNFC50P700X700X100-49A2M; Additional Datasheet URL: N/A; Datasheet URL: http://www.ti.com/lit/ml/mpqf123e/mpqf123e.pdf; Exclusive for Customers: TEXAS INSTRUMENTS NORWAY; Maximum Operating Temperature: +85DEGC; Minimum Operating Temperature: -40DEGC; Mounting Type: SMD; NOTEfied URL: https://notefied-dynamic-precision.com/NOTEfiedWebInterface/part/show?partNumber=18-33969; Notes: Custom component; PCB Package: VQFN48; Part Number: 18-33969; Part Type: IC|MICROCONTROLLER|TEXAS INSTRUMENTS; REACH/SVHC Compliance: Compliant; REACH/SVHC Details: SVHC List Version Jan 12, 2017; REACH/SVHC Source: REACH Declaration; REACH/SVHC Status: Unaffected; ROHS: Compliant; Rated Voltage: 1.8V TO 3.8V; Revision: R004; Status: Released; Texas Part Status: Under Review; Type: IC; Vendor: TEXAS INSTRUMENTS; Vendor Part Status: Preliminary

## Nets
GND: C11.2 C31.2 C33.2 C34.2 C35.2 C41.2 C51.2 C131.2 C132.2 C221.2 C222.2 C231.2 C331.2 C341.2 C342.2 C351.2 C441.2 C451.2 C481.2 J7.2 J7.3 J7.4 J7.5 U1.49(EGP) Y2.2(GND) Y2.4(GND) Z61.2 Z62.2 ; also on sheet 1 2 3 4 5 6
VDDR: C331.1 C451.1 C481.1 L331.2 U1.45(VDDR) U1.48(VDDR_RF)
VDDS: C131.1 C132.1 C221.1 C222.1 C341.1 C342.1 C441.1 FL1.1 R351.2 U1.13(VDDS2) U1.22(VDDS3) U1.34(VDDS_DCDC) U1.44(VDDS)
DCDC_SW: L331.1 U1.33(DCDC_SW)
RX_TX: C31.1 L32.2 U1.3(RX_TX)
WMCU_RESET: C351.1 R351.1 U1.35(RESET_N) ; also on sheet 4 6
WMCU_TCK: U1.25(JTAG_TCKC) ; also on sheet 4 6
WMCU_TMS: U1.24(JTAG_TMSC) ; also on sheet 4 6
WMCU_VDD: FL1.2 ; also on sheet 4 6
N1013277: U1.46(X48M_N) Y2.3
N1014101: C41.1 U1.4(X32K_Q1) Y1.1
N1014113: C51.1 U1.5(X32K_Q2) Y1.2
N1018952: U1.47(X48M_P) Y2.1
N2070550: C231.1 U1.23(DCOUPL)
N2071733: C11.1 L11.1 L12.2 U1.1(RF_P)
N2072219: C21.1 L12.1 L32.1 U1.2(RF_N)
N2075216: C21.2 C33.1 L11.2 L33.1
N2075665: C34.1 L33.2 L34.1
N2076038: C35.1 C36.1 C37.1 L34.2
N2078765: C37.2 J7.1
N2082297: Z60.2 Z61.1 Z62.1 Z63.1
N2245591: A1.1 Z63.2
N2266542: C36.2 Z60.1

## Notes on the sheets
sheet 7
- Wireless MCU RF
- VDDS Decoupling Capacitors
- VDDR Decoupling Capacitors
- Pin 13
- Pin 22
- Pin 44
- Pin 34
- Pin 45
- Pin 48
- Place L331 and
  C331 close to pin 33.
  Low inductance ground for C331
- Z60, Z61, Z62 and Z63 for
  antenna matching
- Mount either C36 or C37
  to select SMA or PCB ant.
- Wireless MCU IO block
  placed on page 2.
- WCS042B
